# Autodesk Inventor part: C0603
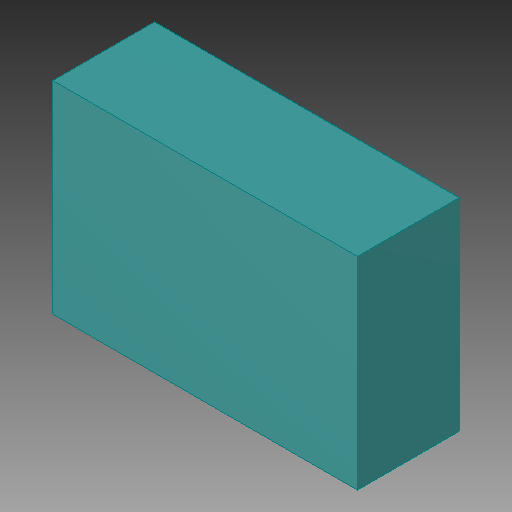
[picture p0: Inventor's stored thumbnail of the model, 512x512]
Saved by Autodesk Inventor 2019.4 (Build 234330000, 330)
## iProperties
Created: 2019-11
Part Number: C0603
Material: Generic
Document SubType Name: Modeling
Designer: Willist
Density: 1 g/cm^3
Appearance: C0603, C0603
Author: Willist
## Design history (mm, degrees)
sketch "C0603, C0603_3"
  geometry: L1 (-1.498, 1.008)-(1.498, 1.008); L2 (1.498, 1.008)-(1.498, -0.983); L3 (1.498, -0.983)-(-1.498, -0.983); L4 (-1.498, -0.983)-(-1.498, 1.008)
  constraints: 8 end point
extrude "Extrusion1" join sketch "C0603, C0603_3" distance "d0" = 1; taper "d1" = 0 deg
body "Solid1"
